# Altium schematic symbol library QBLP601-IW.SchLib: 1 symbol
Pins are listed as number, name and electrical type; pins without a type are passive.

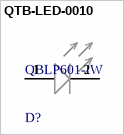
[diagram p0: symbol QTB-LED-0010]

## QTB-LED-0010
designator D?, comment QBLP601-IW
LED WHITE DIFFUSED 0603 SMD; Manufacturer: QT Brightek (QTB); Lens Size: 0.8mm; Luminous Intensity: 330mcd; Test Current: 20mA; Lens Color: Yellow; Lens Style: Flat; Forward Voltage: 3.2V
footprint FP-QBLP601-IW-MFG
pins: 1 ANODE (+), 2 CATHODE (-)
